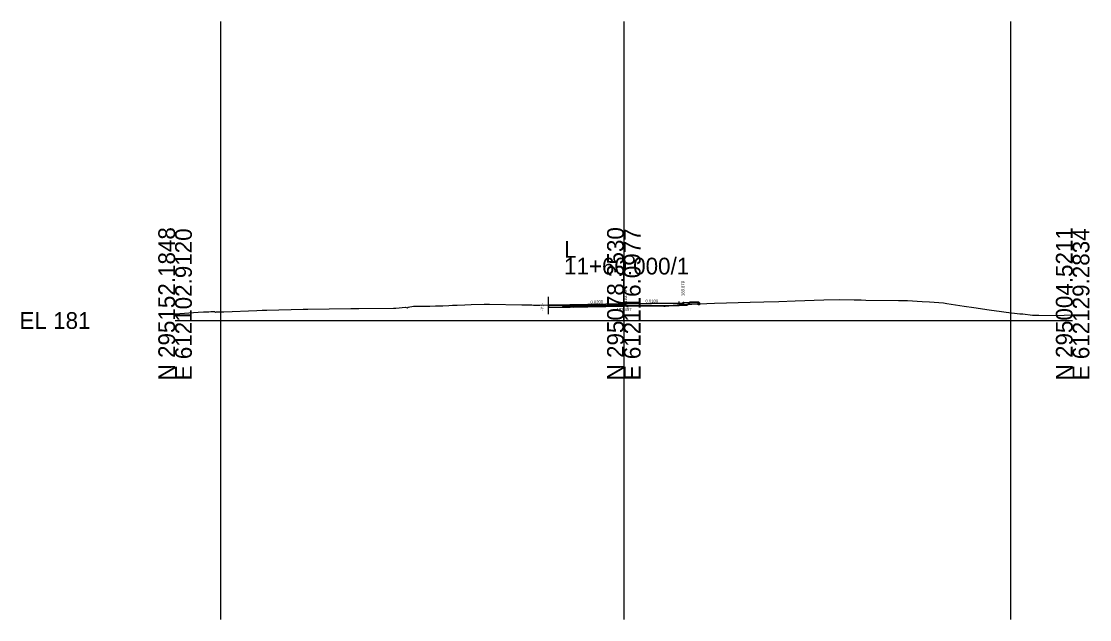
# Model space of a CAD drawing. Extents: x -81 to 616364, y 450 to 299952.
# Drawn here: x 535426.7 to 535605.2, y 118798.4 to 118898.4 of the extents above; entities that cross this region are included whole.
import ezdxf

# ---------------------------------------------------------------- set-up
doc = ezdxf.new("R2010")
doc.units = 0
for name, color, linetype in [('Exist XS Ground Line', 7, 'Continuous'), ('Old_Level_10', 7, 'Continuous'), ('Old_Level_17', 7, 'Continuous'), ('Old_Level_6', 7, 'Continuous'), ('Old_Level_63', 7, 'Continuous'), ('Prop XS Dump Level', 7, 'Continuous'), ('Prop XS Earthwork Shape', 7, 'Continuous'), ('Prop XS EOT Tick Mark', 7, 'Continuous'), ('Prop XS Exc Vertical Line 1', 7, 'Continuous'), ('Prop XS Exc Vertical Line 2', 7, 'Continuous'), ('Prop XS Exc Vertical Line 3', 7, 'Continuous'), ('Prop XS Finish Grade', 7, 'Continuous'), ('Prop XS Finish Grade Concrete', 7, 'Continuous'), ('Prop XS Finish Grade Earthwork', 7, 'Continuous'), ('Prop XS Finish Grade Pavement', 7, 'Continuous'), ('Prop XS Pvmt Edge Slope', 7, 'Continuous'), ('Prop XS Side Slope Text', 7, 'Continuous'), ('Prop XS Subgrade Concrete', 7, 'Continuous'), ('Prop XS Subgrade Earthwork', 7, 'Continuous')]:
    doc.layers.add(name, color=color, linetype=linetype)

msp = doc.modelspace()

# ---------------------------------------------------------------- linework, layer by layer
at = {"layer": 'Exist XS Ground Line'}
for points in [[(535534.29, 118850.78), (535535.54, 118850.85), (535537.56, 118851.03), (535537.68, 118850.99), (535537.87, 118851.12), (535538.04, 118851.12), (535538.18, 118851.11), (535538.7, 118851.11), (535542.49, 118851.27), (535548.49, 118851.44), (535550.78, 118851.5), (535553.26, 118851.54), (535555.98, 118851.65), (535560.76, 118851.82), (535563.37, 118851.86), (535565.87, 118851.82), (535566.56, 118851.8), (535567.02, 118851.8), (535567.78, 118851.78), (535573.28, 118851.72), (535574.79, 118851.68), (535577.21, 118851.56), (535578.47, 118851.51), (535580.77, 118851.33), (535581.36, 118851.22), (535584.22, 118850.78), (535585.83, 118850.54), (535588.42, 118850.14), (535590.47, 118849.88), (535591.28, 118849.76), (535593.55, 118849.5), (535594.04, 118849.46), (535595.66, 118849.24), (535596.21, 118849.24), (535596.69, 118849.24), (535600.1, 118849.22), (535600.96, 118849.26), (535602.36, 118849.33)], [(535452.36, 118849.5), (535456.23, 118849.74), (535457.09, 118849.79), (535457.99, 118849.83), (535458.33, 118849.85), (535458.44, 118849.88), (535458.57, 118849.87), (535458.81, 118849.87), (535458.95, 118849.87), (535459.12, 118849.72), (535459.17, 118849.78), (535459.28, 118849.81), (535460.5, 118849.82), (535466.03, 118850.04), (535466.94, 118850.08), (535467.72, 118850.11), (535473.76, 118850.26), (535474.53, 118850.28), (535478.13, 118850.32), (535481.73, 118850.37), (535483.07, 118850.38), (535488.88, 118850.44), (535489.26, 118850.44), (535490.85, 118850.57), (535491.13, 118850.47), (535491.29, 118850.62), (535491.6, 118850.67), (535491.91, 118850.69), (535492.19, 118850.74), (535492.71, 118850.78), (535494.94, 118850.77), (535495.89, 118850.8), (535497.11, 118850.84), (535498.12, 118850.86), (535498.75, 118850.94), (535499.5, 118850.94), (535500.77, 118850.99), (535501.82, 118851.02), (535504.03, 118851.1), (535504.23, 118851.11), (535504.46, 118851.11), (535504.89, 118851.1), (535510.31, 118850.98), (535510.63, 118850.99), (535511.14, 118851), (535511.69, 118851.01), (535511.97, 118850.99), (535512.28, 118850.95), (535512.59, 118850.94), (535512.94, 118850.93), (535513.32, 118850.95), (535513.76, 118850.96), (535517.13, 118850.85), (535517.32, 118850.69), (535518.3, 118850.74), (535521.38, 118850.8), (535524.49, 118850.86), (535527.36, 118850.86), (535527.79, 118850.86), (535527.91, 118850.86), (535530.73, 118850.82), (535530.84, 118850.82), (535531.08, 118850.82), (535534.04, 118850.76), (535534.29, 118850.78)]]:
    msp.add_lwpolyline(points, dxfattribs=at)
at = {"layer": 'Old_Level_10'}
msp.add_line((535539.78, 118851.26), (535539.78, 118851.42), dxfattribs=at)
at = {"layer": 'Old_Level_17'}
for p, q in [((535539.78, 118851.41), (535539.79, 118851.42)), ((535539.8, 118851.41), (535539.78, 118851.4)), ((535539.79, 118851.42), (535539.83, 118851.42)), ((535539.8, 118851.42), (535539.8, 118851.41)), ((535539.87, 118851.41), (535539.98, 118851.3)), ((535539.78, 118851.27), (535539.98, 118851.27)), ((535539.78, 118850.97), (535539.78, 118851.26)), ((535539.8, 118851.23), (535539.78, 118851.24)), ((535539.78, 118851.21), (535539.8, 118851.23)), ((535539.78, 118851.12), (535539.79, 118851.14)), ((535539.8, 118851.11), (535539.78, 118851.11)), ((535539.98, 118850.97), (535539.78, 118850.97)), ((535539.79, 118851.14), (535539.8, 118851.11)), ((535539.89, 118851.32), (535539.87, 118851.3)), ((535539.87, 118851.3), (535539.92, 118851.31)), ((535539.89, 118851.03), (535539.87, 118851.01)), ((535539.87, 118851.01), (535539.92, 118851.02)), ((535539.92, 118851.31), (535539.89, 118851.32)), ((535539.92, 118851.02), (535539.89, 118851.03)), ((535539.96, 118851.1), (535539.98, 118851.13)), ((535539.98, 118851.11), (535539.96, 118851.1)), ((535539.97, 118851.22), (535539.97, 118851.2)), ((535539.98, 118851.21), (535539.97, 118851.22)), ((535539.97, 118851.2), (535539.98, 118851.2)), ((535539.98, 118851.3), (535539.98, 118850.97)), ((535539.98, 118851.13), (535539.98, 118851.13))]:
    msp.add_line(p, q, dxfattribs=at)
for centre in [(535539.8, 118851.36), (535539.85, 118851.36), (535539.89, 118851.35), (535539.79, 118851.19), (535539.8, 118851.07), (535539.81, 118851.32), (535539.81, 118851.03), (535539.83, 118851.17), (535539.84, 118851.15), (535539.84, 118851.26), (535539.85, 118851.3), (535539.85, 118851.21), (535539.85, 118851.07), (535539.85, 118851.01), (535539.87, 118851.13), (535539.88, 118851.22), (535539.88, 118851.18), (535539.88, 118851.17), (535539.88, 118851.09), (535539.89, 118851.26), (535539.89, 118851.06), (535539.9, 118851.13), (535539.93, 118851.28), (535539.93, 118851.23), (535539.93, 118850.99), (535539.94, 118851.32), (535539.95, 118851.17), (535539.94, 118851.08), (535539.94, 118851.03), (535539.96, 118851.28), (535539.96, 118850.99), (535539.98, 118851.16)]:
    msp.add_circle(centre, 0.00196, dxfattribs=at)
for centre, radius, start, end in [((535539.79, 118851.42), 0.006, 90, 180), ((535539.83, 118851.37), 0.05, 45, 90), ((535539.78, 118851.16), 0.00196, 197.8106, 162.1894), ((535539.84, 118850.97), 0.00196, 342.3416, 197.6584), ((535539.89, 118850.97), 0.00196, 24.915, 155.085), ((535539.98, 118851.07), 0.00196, 76.8767, 283.1233)]:
    msp.add_arc(centre, radius, start, end, dxfattribs=at)
at = {"layer": 'Old_Level_6'}
msp.add_line((535514.76, 118849.4), (535514.76, 118852.31), dxfattribs=at)
at = {"layer": 'Old_Level_63'}
for p, q in [((535527.36, 118848.36), (535527.36, 118858.86)), ((535452.36, 118848.36), (535527.36, 118848.36)), ((535527.36, 118848.36), (535602.36, 118848.36))]:
    msp.add_line(p, q, dxfattribs=at)
at = {"layer": 'Prop XS Dump Level'}
for p, q in [((535514.76, 118850.9), (535518.36, 118850.98)), ((535518.36, 118850.98), (535527.36, 118851.16)), ((535527.36, 118851.16), (535536.63, 118851.25))]:
    msp.add_line(p, q, dxfattribs=at)
at = {"layer": 'Prop XS Earthwork Shape'}
for points in [[(535538.39, 118851.41), (535539.78, 118851.42), (535539.78, 118851.15), (535538.7, 118851.11), (535538.18, 118851.11), (535538.09, 118851.12)], [(535538.09, 118851.12), (535538.18, 118851.11), (535538.7, 118851.11), (535539.78, 118851.15), (535539.78, 118851.42), (535538.39, 118851.41)], [(535538.09, 118851.12), (535538.18, 118851.11), (535538.7, 118851.11), (535539.78, 118851.15), (535539.78, 118851.42), (535538.39, 118851.41)], [(535538.09, 118851.12), (535538.18, 118851.11), (535538.7, 118851.11), (535539.78, 118851.15), (535539.78, 118851.42), (535538.39, 118851.41)], [(535538.09, 118851.12), (535538.18, 118851.11), (535538.7, 118851.11), (535539.78, 118851.15), (535539.78, 118851.42), (535538.39, 118851.41)], [(535538.09, 118851.12), (535538.18, 118851.11), (535538.7, 118851.11), (535539.78, 118851.15), (535539.78, 118851.42), (535538.39, 118851.41)], [(535538.09, 118851.12), (535538.18, 118851.11), (535538.7, 118851.11), (535539.78, 118851.15), (535539.78, 118851.42), (535538.39, 118851.41)], [(535514.76, 118850.52), (535518.19, 118850.59), (535518.18, 118850.73), (535517.32, 118850.69), (535517.13, 118850.85), (535514.76, 118850.93)], [(535514.76, 118850.93), (535517.13, 118850.85), (535517.32, 118850.69), (535518.18, 118850.73), (535518.19, 118850.59), (535514.76, 118850.52)], [(535514.76, 118850.93), (535517.13, 118850.85), (535517.32, 118850.69), (535518.18, 118850.73), (535518.19, 118850.59), (535514.76, 118850.52)], [(535514.76, 118850.93), (535517.13, 118850.85), (535517.32, 118850.69), (535518.19, 118850.73), (535518.19, 118850.59), (535514.76, 118850.52)], [(535514.76, 118850.93), (535517.13, 118850.85), (535517.32, 118850.69), (535518.18, 118850.73), (535518.19, 118850.59), (535514.76, 118850.52)], [(535514.76, 118850.93), (535517.13, 118850.85), (535517.32, 118850.69), (535518.18, 118850.73), (535518.19, 118850.59), (535514.76, 118850.52)], [(535514.76, 118850.93), (535517.13, 118850.85), (535517.32, 118850.69), (535518.18, 118850.73), (535518.19, 118850.59), (535514.76, 118850.52)], [(535518.36, 118850.6), (535527.36, 118850.78), (535531.24, 118850.82), (535531.08, 118850.82), (535530.84, 118850.82), (535530.73, 118850.82), (535527.91, 118850.86), (535527.79, 118850.86), (535527.36, 118850.86), (535524.49, 118850.86), (535521.38, 118850.8), (535518.3, 118850.74), (535518.19, 118850.73), (535518.19, 118850.59)], [(535530.84, 118850.82), (535531.08, 118850.82), (535531.24, 118850.82), (535527.36, 118850.78), (535518.36, 118850.6), (535518.19, 118850.59), (535518.19, 118850.73), (535518.3, 118850.74), (535521.38, 118850.8), (535524.49, 118850.86), (535527.36, 118850.86), (535527.79, 118850.86), (535527.91, 118850.86), (535530.73, 118850.82)], [(535530.84, 118850.82), (535531.08, 118850.82), (535531.24, 118850.82), (535527.36, 118850.78), (535518.36, 118850.6), (535518.19, 118850.59), (535518.19, 118850.73), (535518.3, 118850.74), (535521.38, 118850.8), (535524.49, 118850.86), (535527.36, 118850.86), (535527.79, 118850.86), (535527.91, 118850.86), (535530.73, 118850.82)], [(535530.73, 118850.82), (535530.84, 118850.82), (535531.08, 118850.82), (535531.24, 118850.82), (535527.36, 118850.78), (535518.36, 118850.6), (535518.19, 118850.59), (535518.19, 118850.73), (535518.3, 118850.74), (535521.38, 118850.8), (535524.49, 118850.86), (535527.36, 118850.86), (535527.79, 118850.86), (535527.91, 118850.86)], [(535530.84, 118850.82), (535531.08, 118850.82), (535531.24, 118850.82), (535527.36, 118850.78), (535518.36, 118850.6), (535518.19, 118850.59), (535518.19, 118850.73), (535518.3, 118850.74), (535521.38, 118850.8), (535524.49, 118850.86), (535527.36, 118850.86), (535527.79, 118850.86), (535527.91, 118850.86), (535530.73, 118850.82)], [(535530.84, 118850.82), (535531.08, 118850.82), (535531.24, 118850.82), (535527.36, 118850.78), (535518.36, 118850.6), (535518.19, 118850.59), (535518.19, 118850.73), (535518.3, 118850.74), (535521.38, 118850.8), (535524.49, 118850.86), (535527.36, 118850.86), (535527.79, 118850.86), (535527.91, 118850.86), (535530.73, 118850.82)], [(535527.36, 118850.86), (535527.36, 118850.78), (535518.36, 118850.6), (535518.19, 118850.59), (535518.19, 118850.73), (535518.3, 118850.74), (535521.38, 118850.8), (535524.49, 118850.86)], [(535527.36, 118850.86), (535527.36, 118850.78), (535531.24, 118850.82), (535531.08, 118850.82), (535530.84, 118850.82), (535530.73, 118850.82), (535527.91, 118850.86), (535527.79, 118850.86)], [(535534.29, 118850.78), (535535.54, 118850.85), (535535.6, 118850.86), (535531.24, 118850.82), (535534.04, 118850.76)], [(535531.24, 118850.82), (535534.04, 118850.76), (535534.29, 118850.78), (535535.54, 118850.85), (535535.6, 118850.86)], [(535531.24, 118850.82), (535534.04, 118850.76), (535534.29, 118850.78), (535535.54, 118850.85), (535535.6, 118850.86)], [(535531.24, 118850.82), (535534.04, 118850.76), (535534.29, 118850.78), (535535.54, 118850.85), (535535.6, 118850.86)], [(535531.24, 118850.82), (535534.04, 118850.76), (535534.29, 118850.78), (535535.54, 118850.85), (535535.6, 118850.86)], [(535531.24, 118850.82), (535534.04, 118850.76), (535534.29, 118850.78), (535535.54, 118850.85), (535535.6, 118850.86)], [(535531.24, 118850.82), (535534.04, 118850.76), (535534.29, 118850.78), (535535.54, 118850.85), (535535.6, 118850.86)], [(535535.6, 118850.86), (535536.63, 118850.87), (535537.88, 118850.91), (535538.09, 118851.12), (535538.04, 118851.12), (535537.87, 118851.12), (535537.68, 118850.99), (535537.56, 118851.03)], [(535535.6, 118850.86), (535536.63, 118850.87), (535537.88, 118850.91), (535538.09, 118851.12), (535538.04, 118851.12), (535537.87, 118851.12), (535537.68, 118850.99), (535537.56, 118851.03)], [(535535.6, 118850.86), (535536.63, 118850.87), (535537.88, 118850.91), (535538.09, 118851.12), (535538.04, 118851.12), (535537.87, 118851.12), (535537.68, 118850.99), (535537.56, 118851.03)], [(535535.6, 118850.86), (535536.63, 118850.87), (535537.88, 118850.91), (535538.09, 118851.12), (535538.04, 118851.12), (535537.87, 118851.12), (535537.68, 118850.99), (535537.56, 118851.03)], [(535535.6, 118850.86), (535536.63, 118850.87), (535537.88, 118850.91), (535538.09, 118851.12), (535538.04, 118851.12), (535537.87, 118851.12), (535537.68, 118850.99), (535537.56, 118851.03)], [(535535.6, 118850.86), (535536.63, 118850.87), (535537.88, 118850.91), (535538.09, 118851.12), (535538.04, 118851.12), (535537.87, 118851.12), (535537.68, 118850.99), (535537.56, 118851.03)], [(535535.6, 118850.86), (535536.63, 118850.87), (535537.88, 118850.91), (535538.09, 118851.12), (535538.04, 118851.12), (535537.87, 118851.12), (535537.68, 118850.99), (535537.56, 118851.03)]]:
    msp.add_lwpolyline(points, close=True, dxfattribs=at)
at = {"layer": 'Prop XS EOT Tick Mark'}
msp.add_line((535536.63, 118851.25), (535536.63, 118851.55), dxfattribs=at)
at = {"layer": 'Prop XS Exc Vertical Line 1'}
msp.add_line((535459.94, 118898.36), (535459.94, 118798.36), dxfattribs=at)
at = {"layer": 'Prop XS Exc Vertical Line 2'}
msp.add_line((535527.36, 118898.36), (535527.36, 118798.36), dxfattribs=at)
at = {"layer": 'Prop XS Exc Vertical Line 3'}
msp.add_line((535591.96, 118898.36), (535591.96, 118798.36), dxfattribs=at)
at = {"layer": 'Prop XS Finish Grade'}
msp.add_line((535537.38, 118851.39), (535538.39, 118851.41), dxfattribs=at)
at = {"layer": 'Prop XS Finish Grade Concrete'}
for p, q in [((535537.22, 118851.28), (535537.24, 118851.36)), ((535537.24, 118851.36), (535537.27, 118851.38)), ((535537.3, 118851.39), (535537.27, 118851.38)), ((535537.38, 118851.39), (535537.3, 118851.39)), ((535536.63, 118851.25), (535537.15, 118851.24)), ((535537.15, 118851.24), (535537.19, 118851.25)), ((535537.19, 118851.25), (535537.22, 118851.28))]:
    msp.add_line(p, q, dxfattribs=at)
at = {"layer": 'Prop XS Finish Grade Earthwork'}
for p, q in [((535538.39, 118851.41), (535539.78, 118851.42)), ((535539.78, 118851.42), (535539.78, 118851.15))]:
    msp.add_line(p, q, dxfattribs=at)
at = {"layer": 'Prop XS Finish Grade Pavement'}
for p, q in [((535518.36, 118850.98), (535514.76, 118850.9)), ((535527.36, 118851.16), (535518.36, 118850.98)), ((535536.63, 118851.25), (535527.36, 118851.16))]:
    msp.add_line(p, q, dxfattribs=at)
at = {"layer": 'Prop XS Pvmt Edge Slope'}
for p, q in [((535537.38, 118851.09), (535537.68, 118851.1)), ((535537.68, 118851.1), (535537.88, 118850.91))]:
    msp.add_line(p, q, dxfattribs=at)
at = {"layer": 'Prop XS Subgrade Concrete'}
for p, q in [((535537.38, 118851.09), (535537.38, 118851.39)), ((535536.63, 118851.25), (535536.63, 118851.07)), ((535536.63, 118851.07), (535537.38, 118851.09))]:
    msp.add_line(p, q, dxfattribs=at)
at = {"layer": 'Prop XS Subgrade Earthwork'}
for p, q in [((535537.88, 118850.91), (535538.39, 118851.41)), ((535514.76, 118850.52), (535514.76, 118850.93)), ((535514.76, 118850.52), (535518.19, 118850.59)), ((535518.19, 118850.59), (535518.18, 118850.73)), ((535518.19, 118850.73), (535518.19, 118850.59)), ((535518.19, 118850.59), (535518.36, 118850.6)), ((535518.36, 118850.6), (535527.36, 118850.78)), ((535527.36, 118850.78), (535536.63, 118850.87)), ((535536.63, 118850.87), (535537.88, 118850.91))]:
    msp.add_line(p, q, dxfattribs=at)

# ---------------------------------------------------------------- texts
at = {"layer": 'Old_Level_63'}
for s, p in [('N 295152.1848', (535452.36, 118838.36)), ('E 612102.9120', (535455.16, 118838.36)), ('N 295078.3530', (535527.36, 118838.36)), ('E 612116.0977', (535530.16, 118838.36)), ('N 295004.5211', (535602.36, 118838.36)), ('E 612129.2834', (535605.16, 118838.36))]:
    msp.add_text(s, height=2.8, rotation=90, dxfattribs=at).set_placement(p)
for s, p in [('L', (535517.36, 118858.86)), ('11+60.000/1', (535517.36, 118856.06)), ('EL 181', (535426.36, 118846.96))]:
    msp.add_text(s, height=2.8, dxfattribs=at).set_placement(p)
at = {"layer": 'Prop XS Dump Level'}
msp.add_text('Eop', height=0.3, dxfattribs=at).set_placement((535518.19, 118850.43))
at = {"layer": 'Prop XS Side Slope Text'}
for s, rotation, p in [(' 183.79', 90, (535527.86, 118851.16)), ('183.879', 90, (535537.48, 118852.46)), ('0.0200', 1.1458, (535521.79, 118851.2)), ('0.0100', 0.5729, (535530.98, 118851.35)), ('-Y1-', 90, (535513.96, 118849.99))]:
    msp.add_text(s, height=0.5, rotation=rotation, dxfattribs=at).set_placement(p)
msp.add_text('183.497', height=0.5, dxfattribs=at).set_placement((535526.15, 118849.96))

doc.saveas('drawing.dxf')
